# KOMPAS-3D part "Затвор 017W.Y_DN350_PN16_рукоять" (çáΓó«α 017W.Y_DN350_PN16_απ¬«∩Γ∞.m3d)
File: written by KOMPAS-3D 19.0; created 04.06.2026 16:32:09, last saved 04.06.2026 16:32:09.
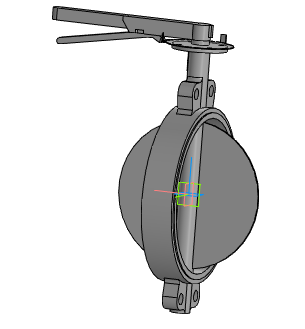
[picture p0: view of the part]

Document properties: Автор: Энергия; Полное имя файла: ..\..\..\3d для проектировщиков\017W разные\x.x Тип 017W.Y(S) Затвор дисковый поворотный межфланцевый\Затвор 017W.Y(S)_DN32-DN350_рукоять\Затвор 017W.Y_DN350_PN16_рукоять.a3d

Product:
- Part/product: Затвор 017W.Y_DN350_PN16_рукоять
    Масса: 33.0786

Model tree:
1. Операция без истории:1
